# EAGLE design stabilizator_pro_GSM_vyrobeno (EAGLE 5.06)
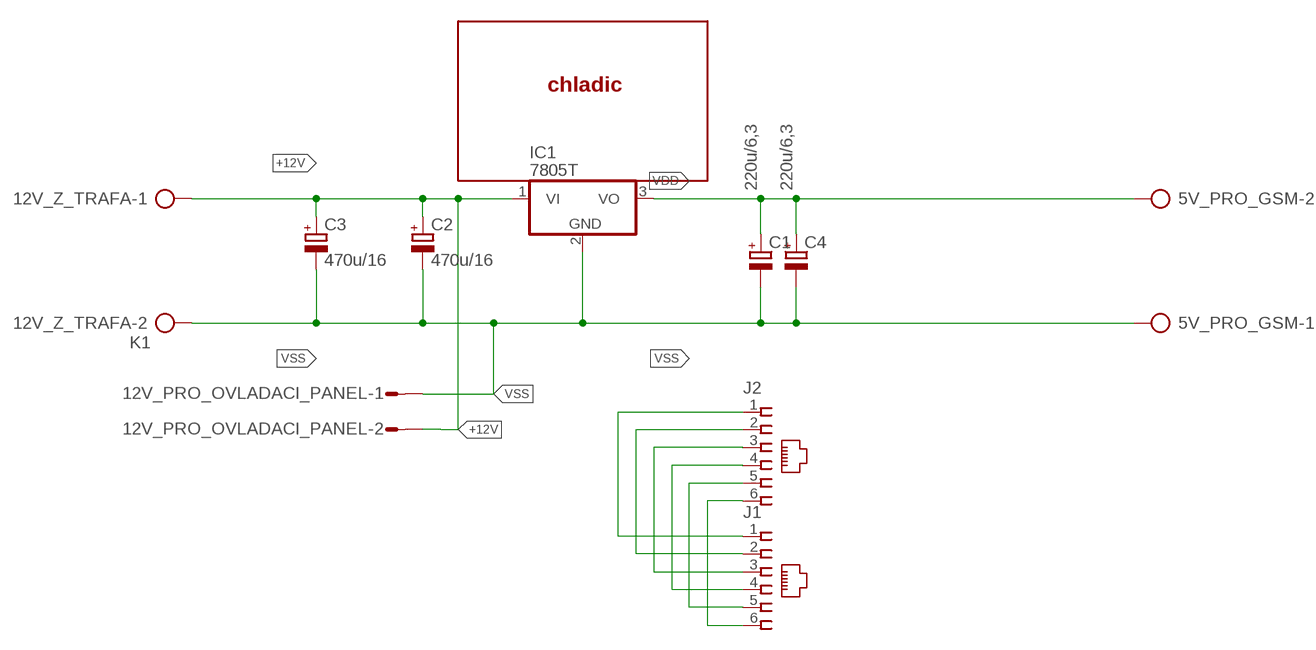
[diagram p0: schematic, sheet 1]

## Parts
5V_PRO_GSM  AK500/2-H  [AK500/2-H]
12V_PRO_OVLADACI_PANEL  L02P  [L02P]
12V_Z_TRAFA  K1  AK500/2-H  [AK500/2-H]
C1  220u/6,3  CPOL-EUE2,5-6E  [E2,5-6E]
C2  470u/16  CPOL-EUE2,5-6E  [E2,5-6E]
C3  470u/16  CPOL-EUE2,5-6E  [E2,5-6E]
C4  220u/6,3  CPOL-EUE2,5-6E  [E2,5-6E]
IC1  7805T  [TO220H]
J1  520250-3  [520250-3]
J2  520250-3  [520250-3]
U$1  CHLAD  [MALI_CHLADIC]

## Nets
+12V: 12V_PRO_OVLADACI_PANEL.2 12V_Z_TRAFA.1 C2.+ C3.+ IC1.1(VI)
N$1: J1.6 J2.6
N$2: J1.5 J2.5
N$4: J1.3 J2.3
N$5: J1.2 J2.2
N$6: J1.1 J2.1
VDD: 5V_PRO_GSM.2 C1.+ C4.+ IC1.3(VO)
VSS: 5V_PRO_GSM.1 12V_PRO_OVLADACI_PANEL.1 12V_Z_TRAFA.2 C1.- C2.- C3.- C4.- IC1.2(GND) J1.4 J2.4

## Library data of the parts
5V_PRO_GSM 12V_Z_TRAFA = con-ptr500:AK500/2-H: CONNECTOR
12V_PRO_OVLADACI_PANEL = con-amp-mt:L02P: AMP MT CONNECTOR
C1-C4 = rcl:CPOL-EU: POLARIZED CAPACITOR, European symbol
IC1 = linear:78*: Positive VOLTAGE REGULATOR Source: http://cache.national.com/ds/LM/LM78L05.pdf http://www.fairchildsemi.com/ds/LM/LM7805.pdf
J1 J2 = con-amp:520250-3: AMP connector
U$1 = chladic_TO220:CHLAD: chladic pro pouydro TO220

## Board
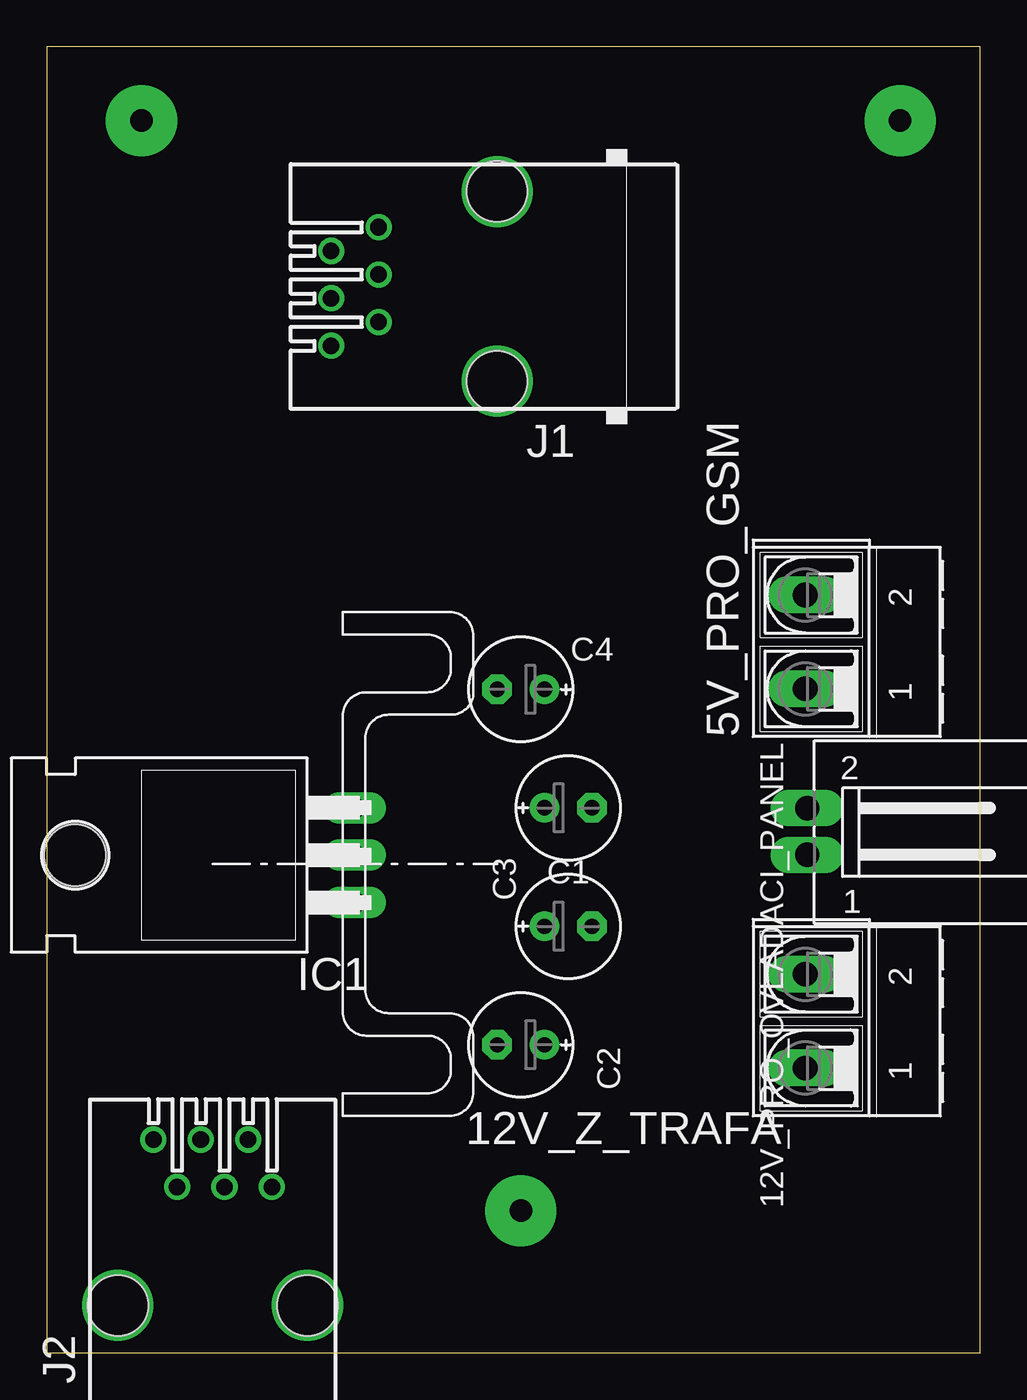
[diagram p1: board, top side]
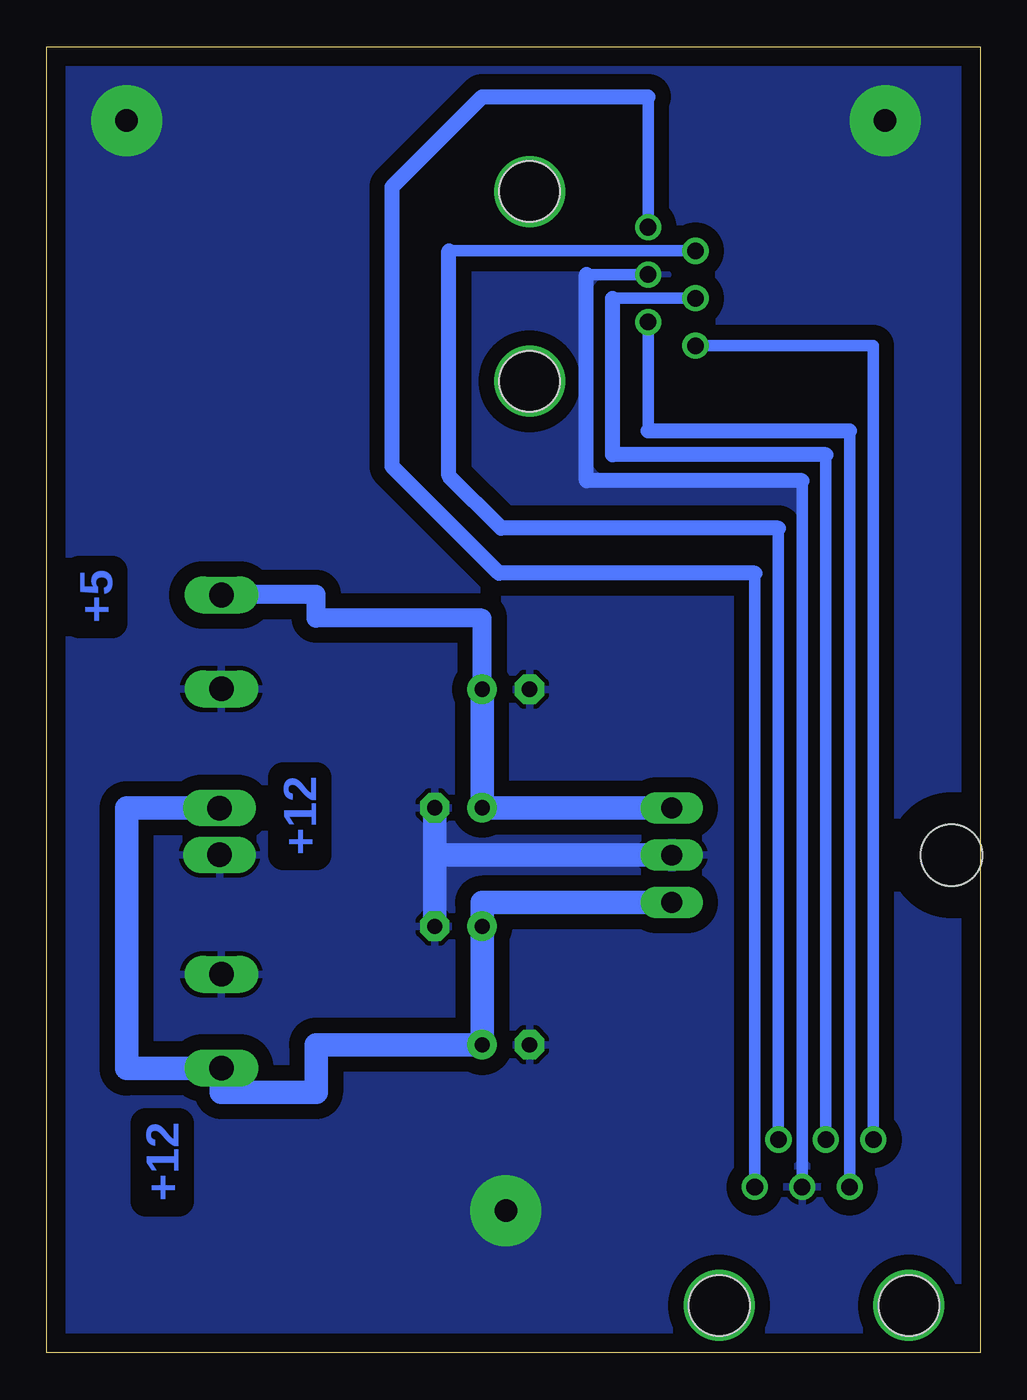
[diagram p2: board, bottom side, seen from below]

Size 50 x 70 mm. Coordinates in mm from the lower left corner, seen from the top.
Outline: 50,0 50,70 0,70 0,0 50,0
Copper layers (1*16): Top 0.035mm / dielectric 1.5mm / Bottom 0.035mm
Design rules "default": minimum track width 10mil, minimum drill 24mil, track to track 8mil, track to pad 8mil, pad to pad 8mil, via to via 8mil, smd to smd 8mil, copper to edge 40mil, drill to drill 8mil, minimum pad ring 10mil, minimum via ring 8mil, stop-mask expansion 4mil, vias tented up to drill 0mil, thermal gap 10mil

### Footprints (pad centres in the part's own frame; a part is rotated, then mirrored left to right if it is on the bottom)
AK500/2-H = drill 1.321 long: 1 -2.515,0; 2 2.515,0
L02P = drill 1.3 long: 1 1.25,-6.25; 2 -1.25,-6.25
E2,5-6E = drill 0.813 pad 1.575 round: + -1.27,0 | drill 0.813 pad 1.575 octagon: - 1.27,0
TO220H = drill 1.118 long: 1 -2.54,-10.16; 2 0,-10.16; 3 2.54,-10.16 | hole 3.302: 0,4.826
520250-3 = drill 0.889 round: 1 -3.175,8.89; 2 -1.905,6.35; 3 -0.635,8.89; 4 0.635,6.35; 5 1.905,8.89; 6 3.175,6.35 | hole 3.251: -5.08,0; 5.08,0

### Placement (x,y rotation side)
5V_PRO_GSM  40.64,38.1 90 top
12V_PRO_OVLADACI_PANEL  46.99,27.94 270 top
12V_Z_TRAFA  40.64,17.78 90 top
C1  27.94,29.21 0 top
C2  25.4,16.51 180 top
C3  27.94,22.86 0 top
C4  25.4,35.56 180 top
IC1  6.35,26.67 90 top
J1  24.13,57.15 90 top
J2  8.89,2.54 0 top
U$1  19.05,12.7 90 top

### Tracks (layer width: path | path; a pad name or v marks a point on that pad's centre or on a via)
+12V
  Bottom 1.27: IC1.1 26.67,24.13 C3.+ C2.+ 35.56,16.51 35.56,13.97 40.64,13.97 12V_Z_TRAFA.1 40.64,15.24 45.72,15.24 45.72,29.19 12V_PRO_OVLADACI_PANEL.2
N$1
  Bottom 0.61: J2.6 12.06,41.78 | 17.78,67.31 J1.6
  Bottom 0.813: 12.06,41.78 25.78,41.78 31.5,47.5 31.5,62.48 26.67,67.31 17.78,67.31
N$2
  Bottom 0.61: 28.45,59.05 J1.5 | J2.5 10.79,44.2
  Bottom 0.813: 28.45,59.05 28.45,46.99 25.65,44.2 10.79,44.2
N$4
  Bottom 0.61: J2.3 8.26,48.13 | 19.68,56.52 J1.3
  Bottom 0.813: 8.26,48.13 19.68,48.13 19.68,56.52
N$5
  Bottom 0.61: J2.2 6.99,49.4 | 17.78,49.4 J1.2
  Bottom 0.813: 6.99,49.4 17.78,49.4
N$6
  Bottom 0.61: J2.1 5.71,53.98 J1.1
N$10  (via drill 1.2 pad 3.81)
  other vias: 24.13,62.23
N$11  (via drill 1.2 pad 3.81)
  other vias: 24.13,52.07
N$12  (via drill 1.2 pad 3.81)
  other vias: 13.97,2.54
N$13  (via drill 1.2 pad 3.81)
  other vias: 3.81,2.54
VDD
  Bottom 1.016: C4.+ 26.67,39.37 35.56,39.37 35.56,40.64 40.64,40.64
  Bottom 1.27: IC1.3 C1.+ C4.+ | 40.64,40.64 5V_PRO_GSM.2
VSS  (via drill 1.2 pad 3.81)
  Bottom 0.61: J2.4 9.53,46.74 | 21.08,57.78 J1.4
  Bottom 0.813: 9.53,46.74 21.08,46.74 21.08,57.78
  Bottom 1.27: 29.21,26.67 C3.- | 29.21,26.67 C1.- | IC1.2 29.21,26.67
  other vias: 5.08,66.04 45.72,66.04 25.4,7.62
  pour Bottom (isolate 0.813): 0,70 50,70 50,0 0,0

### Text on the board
Bottom: +5 | +12 | +12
